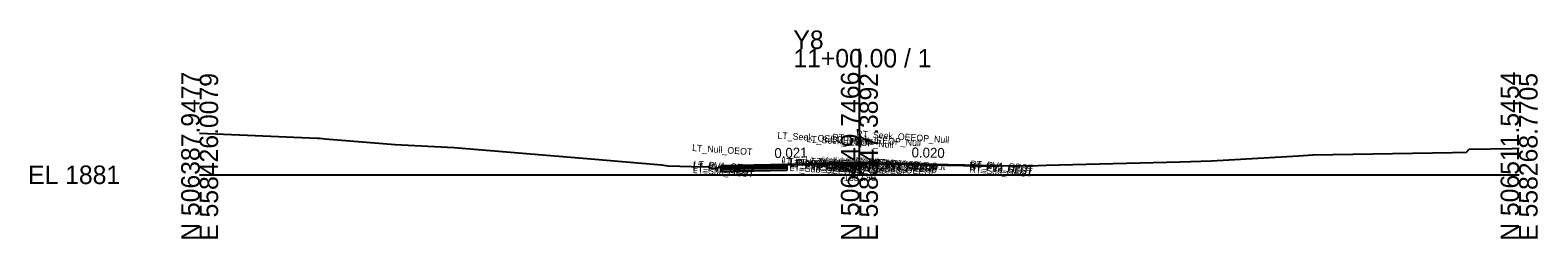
# Model space of a CAD drawing. Extents: x -26 to 203, y -10 to 8070.
# Drawn here: x -25.7 to 202.8, y 990.3 to 1021.9 of the extents above; entities that cross this region are included whole.
import ezdxf

# ---------------------------------------------------------------- set-up
doc = ezdxf.new("R2010")
doc.units = 0
for name, color, linetype in [('Default', 7, 'Continuous'), ('Exist Cross Section Cell', 7, 'Continuous'), ('Exist XS Center Line Elevation Label', 7, 'Continuous'), ('Exist XS Ground Line', 7, 'Continuous'), ('Prop CMT Pvmt Course 1', 7, 'Continuous'), ('Prop CMT Pvmt Course 2', 7, 'Continuous'), ('Prop CMT Pvmt Course 3', 7, 'Continuous'), ('Prop CMT Pvmt Surface', 7, 'Continuous'), ('Prop CMT Subgrade Earthwork', 7, 'Continuous'), ('Prop XS Earthwork Shape', 7, 'Continuous'), ('Prop XS SE Text', 7, 'Continuous'), ('Typical Text Grade Point CELL', 7, 'Continuous')]:
    doc.layers.add(name, color=color, linetype=linetype)

msp = doc.modelspace()

# ---------------------------------------------------------------- linework, layer by layer
at = {"layer": 'Exist Cross Section Cell'}
for p, q in [((100, 1000), (100, 1019.04)), ((0, 1000), (100, 1000)), ((100, 1000), (200, 1000))]:
    msp.add_line(p, q, dxfattribs=at)
at = {"layer": 'Exist XS Ground Line'}
for p, q in [((0, 1006.29), (7.24, 1005.98)), ((7.24, 1005.98), (17.81, 1005.55)), ((17.81, 1005.55), (18.21, 1005.52)), ((18.21, 1005.52), (19.04, 1005.46)), ((19.04, 1005.46), (29.61, 1004.6)), ((29.61, 1004.6), (38.59, 1004.11)), ((38.59, 1004.11), (59.27, 1002.4)), ((168.72, 1003), (189.88, 1003.39)), ((189.88, 1003.39), (192.03, 1003.43)), ((192.03, 1003.43), (192.41, 1003.87)), ((192.41, 1003.87), (198.97, 1003.99)), ((198.97, 1003.99), (200, 1004.02)), ((59.27, 1002.4), (70.02, 1001.51)), ((70.02, 1001.51), (71, 1001.33)), ((71, 1001.33), (74.56, 1001.24)), ((74.56, 1001.24), (75, 1001.22)), ((75, 1001.22), (77.05, 1001.23)), ((77.05, 1001.23), (77.68, 1000.91)), ((77.68, 1000.91), (79.13, 1001.18)), ((79.13, 1001.18), (87.01, 1001.52)), ((87.01, 1001.52), (100, 1001.8)), ((100, 1001.8), (100.46, 1001.81)), ((100.46, 1001.81), (100.89, 1001.82)), ((100.89, 1001.82), (120.89, 1001.39)), ((120.89, 1001.39), (121.59, 1001.39)), ((121.59, 1001.39), (125.88, 1001.37)), ((125.88, 1001.37), (128.32, 1001.46)), ((128.32, 1001.46), (148.56, 1001.97)), ((148.56, 1001.97), (153.36, 1002.11)), ((153.36, 1002.11), (166.58, 1002.87)), ((166.58, 1002.87), (168.72, 1003))]:
    msp.add_line(p, q, dxfattribs=at)
at = {"layer": 'Prop CMT Pvmt Course 1'}
for points in [[(100, 1001.8), (98, 1001.76), (97.99, 1001.76), (94.01, 1001.67), (94, 1001.67), (79, 1001.35)], [(79, 1001.35), (79, 1001.1)], [(79, 1001.1), (89, 1001.31)], [(100, 1001.8), (102, 1001.79), (102.01, 1001.79), (105.99, 1001.7), (106, 1001.7), (121, 1001.38)]]:
    msp.add_lwpolyline(points, dxfattribs=at)
at = {"layer": 'Prop CMT Pvmt Course 2'}
for points in [[(89, 1001.31), (79, 1001.1)], [(79, 1001.1), (79, 1000.85)], [(79, 1000.85), (89, 1001.06)]]:
    msp.add_lwpolyline(points, dxfattribs=at)
at = {"layer": 'Prop CMT Pvmt Course 3'}
for points in [[(89, 1001.06), (79, 1000.85)], [(79, 1000.85), (79, 1000.47)], [(79, 1000.47), (89, 1000.69)]]:
    msp.add_lwpolyline(points, dxfattribs=at)
at = {"layer": 'Prop CMT Pvmt Surface'}
for points in [[(100, 1001.8), (98, 1001.76), (97.99, 1001.76), (94.01, 1001.67), (94, 1001.67), (79, 1001.35)], [(100, 1001.8), (102, 1001.79), (102.01, 1001.79), (105.99, 1001.7), (106, 1001.7), (121, 1001.38)]]:
    msp.add_lwpolyline(points, dxfattribs=at)
at = {"layer": 'Prop CMT Subgrade Earthwork'}
for points in [[(79, 1000.47), (79, 1001.16)], [(89, 1000.69), (89, 1001.56)], [(89, 1000.69), (79, 1000.47)]]:
    msp.add_lwpolyline(points, dxfattribs=at)
at = {"layer": 'Prop XS Earthwork Shape'}
for points in [[(102, 1001.79), (105.99, 1001.7), (120.89, 1001.39), (121, 1001.38), (121, 1001.26), (100, 1001.67), (89, 1001.44), (89, 1000.69), (79, 1000.47), (79, 1001.16), (79.13, 1001.18), (87.01, 1001.52), (94.01, 1001.67), (98, 1001.76), (100, 1001.8)], [(100, 1001.8), (102, 1001.79), (100.89, 1001.82), (100.46, 1001.81)]]:
    msp.add_lwpolyline(points, close=True, dxfattribs=at)

# ---------------------------------------------------------------- texts
at = {"layer": 'Default'}
msp.add_text('-', height=0.0001, dxfattribs=at).set_placement((0, 1000))
at = {"layer": 'Exist Cross Section Cell'}
for s, p in [('Y8', (90, 1019.04)), ('11+00.00 / 1', (90, 1016.24)), ('EL 1881', (-26, 998.6))]:
    msp.add_text(s, height=2.8, dxfattribs=at).set_placement(p)
for s, p in [('N 506387.9477', (0, 990)), ('E 558426.0079', (2.8, 990)), ('N 506449.7466', (100, 990)), ('E 558347.3892', (102.8, 990)), ('N 506511.5454', (200, 990)), ('E 558268.7705', (202.8, 990))]:
    msp.add_text(s, height=2.8, rotation=90, dxfattribs=at).set_placement(p)
at = {"layer": 'Exist XS Center Line Elevation Label'}
msp.add_text('1882.80', height=1, dxfattribs=at).set_placement((97.67, 999.05))
at = {"layer": 'Prop XS SE Text'}
for s, rotation, p in [('0.021', 1.2278, (87.13, 1002.52)), ('0.020', 358.8616, (107.9, 1002.64))]:
    msp.add_text(s, height=1.5, rotation=rotation, dxfattribs=at).set_placement(p)
at = {"layer": 'Typical Text Grade Point CELL'}
for s, p in [('LT_Seek_OEEOP_Null', (87.55, 1005.49)), ('LT_Seek_IEEOP_Null', (91.93, 1004.96)), ('RT_Seek_IEEOP_Null', (95.87, 1005.22)), ('RT_Seek_OEEOP_Null', (99.49, 1005.74)), ('LT_Null_OEOT', (74.62, 1003.6)), ('LT_PV2_OEOT', (74.72, 1000.9)), ('LT_PV3_OEOT', (74.72, 1000.65)), ('LT_Sub_OEOT', (74.74, 1000.27)), ('LT_PV1_OEOT', (74.84, 1001.14)), ('LT_PV_Sub_Tie_Out', (88.14, 1001.58)), ('LT_Null OEEOP Test', (88.4, 1001.61)), ('LT_PV2_OEEOP', (89.37, 1001.24)), ('LT_PV3_OEEOP', (89.37, 1000.99)), ('LT_Sub_OEEOP', (89.39, 1000.61)), ('LT_PV1_OEEOP', (89.49, 1001.36)), ('LT_Pvmt Out', (90.25, 1001.43)), ('LT_Null IEEOP Test', (91.78, 1001.64)), ('LT_PV_Sub_Tie_In', (92.76, 1001.62)), ('LT_PV2_IEEOP', (93.75, 1001.3)), ('LT_PV3_IEEOP', (93.75, 1001.05)), ('LT_Sub_IEEOP', (93.77, 1000.67)), ('LT_PV1_IEEOP', (93.87, 1001.42)), ('Null RT Pvmt Slope', (94.26, 1001.74)), ('Null LT Pvmt Slope', (94.32, 1001.69)), ('PV1_Overlay_Null', (94.75, 1001.54)), ('LT_Pvmt In', (94.84, 1001.47)), ('RT_PV_Sub_Tie_In', (96.7, 1001.66)), ('RT_Null IEEOP Test', (96.72, 1001.68)), ('Sub_PGL', (97.35, 1000.61)), ('PV2_PGL', (97.32, 1001.23)), ('PV3_PGL', (97.32, 1000.98)), ('PV1_PGL', (97.44, 1001.48)), ('RT_PV2_IEEOP', (97.69, 1001.31)), ('RT_PV3_IEEOP', (97.69, 1001.06)), ('RT_Sub_IEEOP', (97.71, 1000.68)), ('RT_PV1_IEEOP', (97.81, 1001.42)), ('RT_Pvmt In', (98.8, 1001.51)), ('CL', (99.2, 1001.35)), ('RT_Null OEEOP Test', (99.34, 1001.64)), ('RT_PV_Sub_Tie_Out', (100.09, 1001.61)), ('RT_PV2_OEEOP', (101.31, 1001.25)), ('RT_PV3_OEEOP', (101.31, 1001)), ('RT_Sub_OEEOP', (101.33, 1000.63)), ('RT_PV1_OEEOP', (101.43, 1001.37)), ('RT_Pvmt Out', (102.17, 1001.47)), ('RT_PV2_OEOT', (116.66, 1000.93)), ('RT_PV3_OEOT', (116.66, 1000.68)), ('RT_Sub_OEOT', (116.69, 1000.31)), ('RT_PV1_OEOT', (116.78, 1001.17))]:
    msp.add_text(s, height=1, rotation=356, dxfattribs=at).set_placement(p)

doc.saveas('drawing.dxf')
